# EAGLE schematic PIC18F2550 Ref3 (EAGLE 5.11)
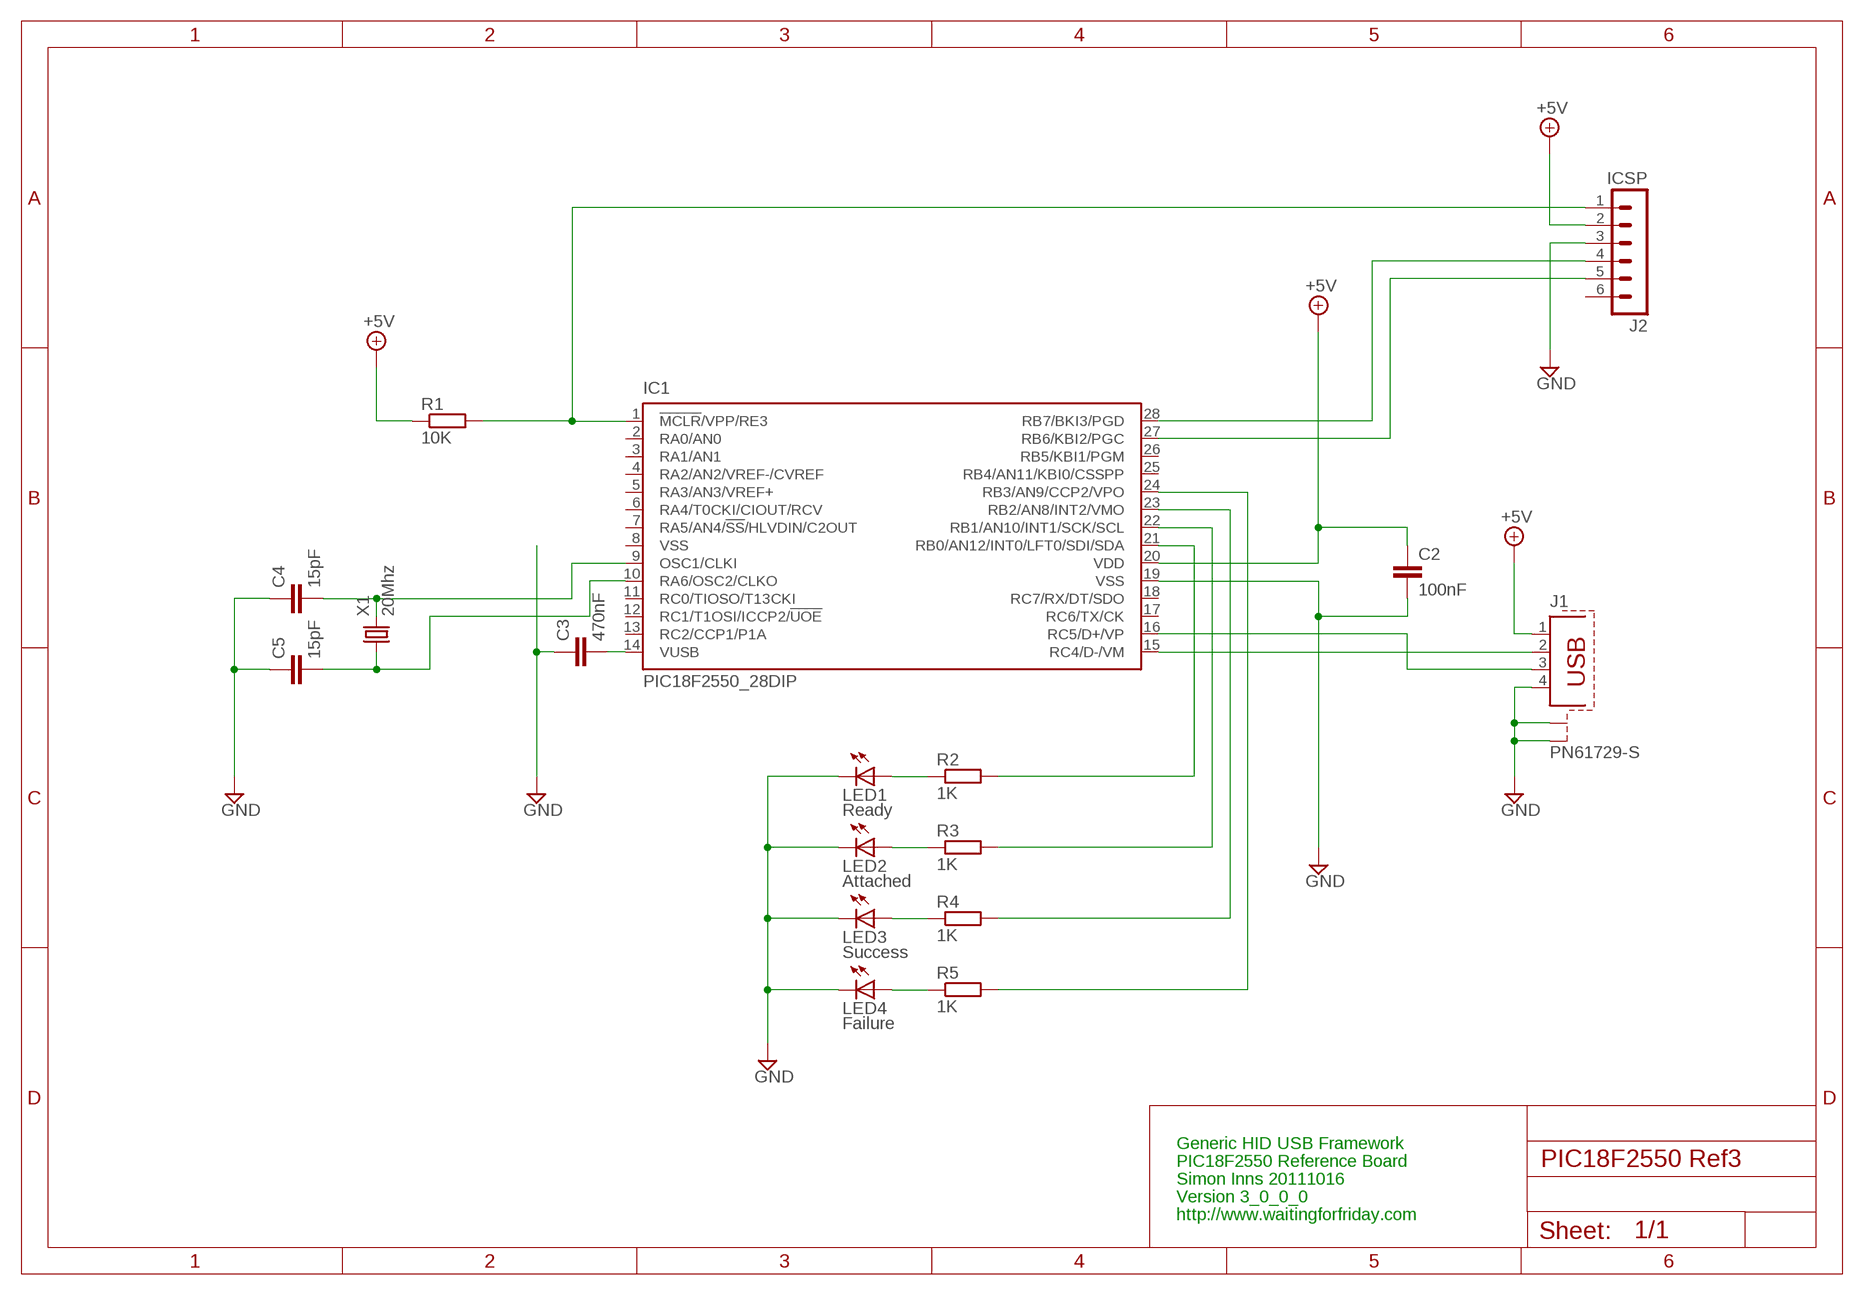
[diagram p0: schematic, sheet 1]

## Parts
C2  100nF  C-EU075-032X103  [C075-032X103]
C3  470nF  C-EU050-045X075  [C050-045X075]
C4  15pF  C-EU050-024X044  [C050-024X044]
C5  15pF  C-EU050-024X044  [C050-024X044]
IC1  PIC18F2550_28DIP  [DIL28-3]
J1  PN61729-S  [PN61729-S]
J2  ICSP  MA06-1  [MA06-1]
LED1  Ready  LED3MM  [LED3MM]
LED2  Attached  LED3MM  [LED3MM]
LED3  Success  LED3MM  [LED3MM]
LED4  Failure  LED3MM  [LED3MM]
R1  10K  R-EU_0207/10  [0207/10]
R2  1K  R-EU_0207/10  [0207/10]
R3  1K  R-EU_0207/10  [0207/10]
R4  1K  R-EU_0207/10  [0207/10]
R5  1K  R-EU_0207/10  [0207/10]
X1  20Mhz  CRYSTALHC49U-V  [HC49U-V]

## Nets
+5V: C2.1 IC1.20(VDD) J1.1 J2.2 R1.1
GND: C2.2 C3.1 C4.1 C5.1 IC1.19(VSS) J1.4 J1.S1 J1.S2 J2.3 LED1.K(C) LED2.K(C) LED3.K(C) LED4.K(C)
N$1: IC1.1(!MCLR!/VPP/RE3) J2.1 R1.2
N$2: LED1.A R2.1
N$3: LED2.A R3.1
N$4: LED3.A R4.1
N$5: LED4.A R5.1
N$6: C4.2 IC1.9(OSC1/CLKI) X1.2
N$7: C5.2 IC1.10(RA6/OSC2/CLKO) X1.1
N$8: IC1.21(RB0/AN12/INT0/LFT0/SDI/SDA) R2.2
N$9: IC1.28(RB7/BKI3/PGD) J2.4
N$10: IC1.27(RB6/KBI2/PGC) J2.5
N$11: C3.2 IC1.14(VUSB)
N$12: IC1.15(RC4/D-/VM) J1.2
N$13: IC1.16(RC5/D+/VP) J1.3
N$14: IC1.22(RB1/AN10/INT1/SCK/SCL) R3.2
N$15: IC1.23(RB2/AN8/INT2/VMO) R4.2
N$16: IC1.24(RB3/AN9/CCP2/VPO) R5.2
Unconnected: IC1.2(RA0/AN0) IC1.3(RA1/AN1) IC1.4(RA2/AN2/VREF-/CVREF) IC1.5(RA3/AN3/VREF+) IC1.6(RA4/T0CKI/CIOUT/RCV) IC1.7(RA5/AN4/!SS!/HLVDIN/C2OUT) IC1.11(RC0/TIOSO/T13CKI) IC1.12(RC1/T1OSI/ICCP2/!UOE) IC1.13(RC2/CCP1/P1A) IC1.17(RC6/TX/CK) IC1.18(RC7/RX/DT/SDO) IC1.25(RB4/AN11/KBI0/CSSPP) IC1.26(RB5/KBI1/PGM) J2.6

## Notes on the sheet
- Generic HID USB Framework
- PIC18F2550 Reference Board
- Simon Inns 20111016
- Version 3_0_0_0
- http://www.waitingforfriday.com

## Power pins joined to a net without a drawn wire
VSS: IC1.8(VSS)

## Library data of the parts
C2-C5 = rcl:C-EU: CAPACITOR, European symbol
IC1 = microchip:PIC18F2*_28: USB Microcontrollers with nanoWatt Technology High-Performance, Enhanced Flash, 28/40/44-Pin, Source: http://ww1.microchip.com/downloads/en/devicedoc/39632c.pdf; MF: MICROCHIP; MPN: PIC18F2550-I/SP; OC_FARNELL: 1523822; OC_NEWARK: 80K6054
J1 = con-berg:PN61729-S: BERG USB connector; OC_FARNELL: unknown; OC_NEWARK: unknown
J2 = con-lstb:MA06-1: PIN HEADER; OC_FARNELL: unknown; OC_NEWARK: unknown
LED1-LED4 = led:LED: LED
R1-R5 = rcl:R-EU_: RESISTOR, European symbol
X1 = crystal:CRYSTAL: CRYSTAL; OC_FARNELL: 1666969; OC_NEWARK: unknown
